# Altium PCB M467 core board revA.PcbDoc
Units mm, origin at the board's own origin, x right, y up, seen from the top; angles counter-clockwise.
Board outline 29.95 x 52.05 mm, 2 copper layers (Top Layer, Bottom Layer), stack 0.98 mm thick; 44 components, 41 nets, 229 pads, 86 vias.
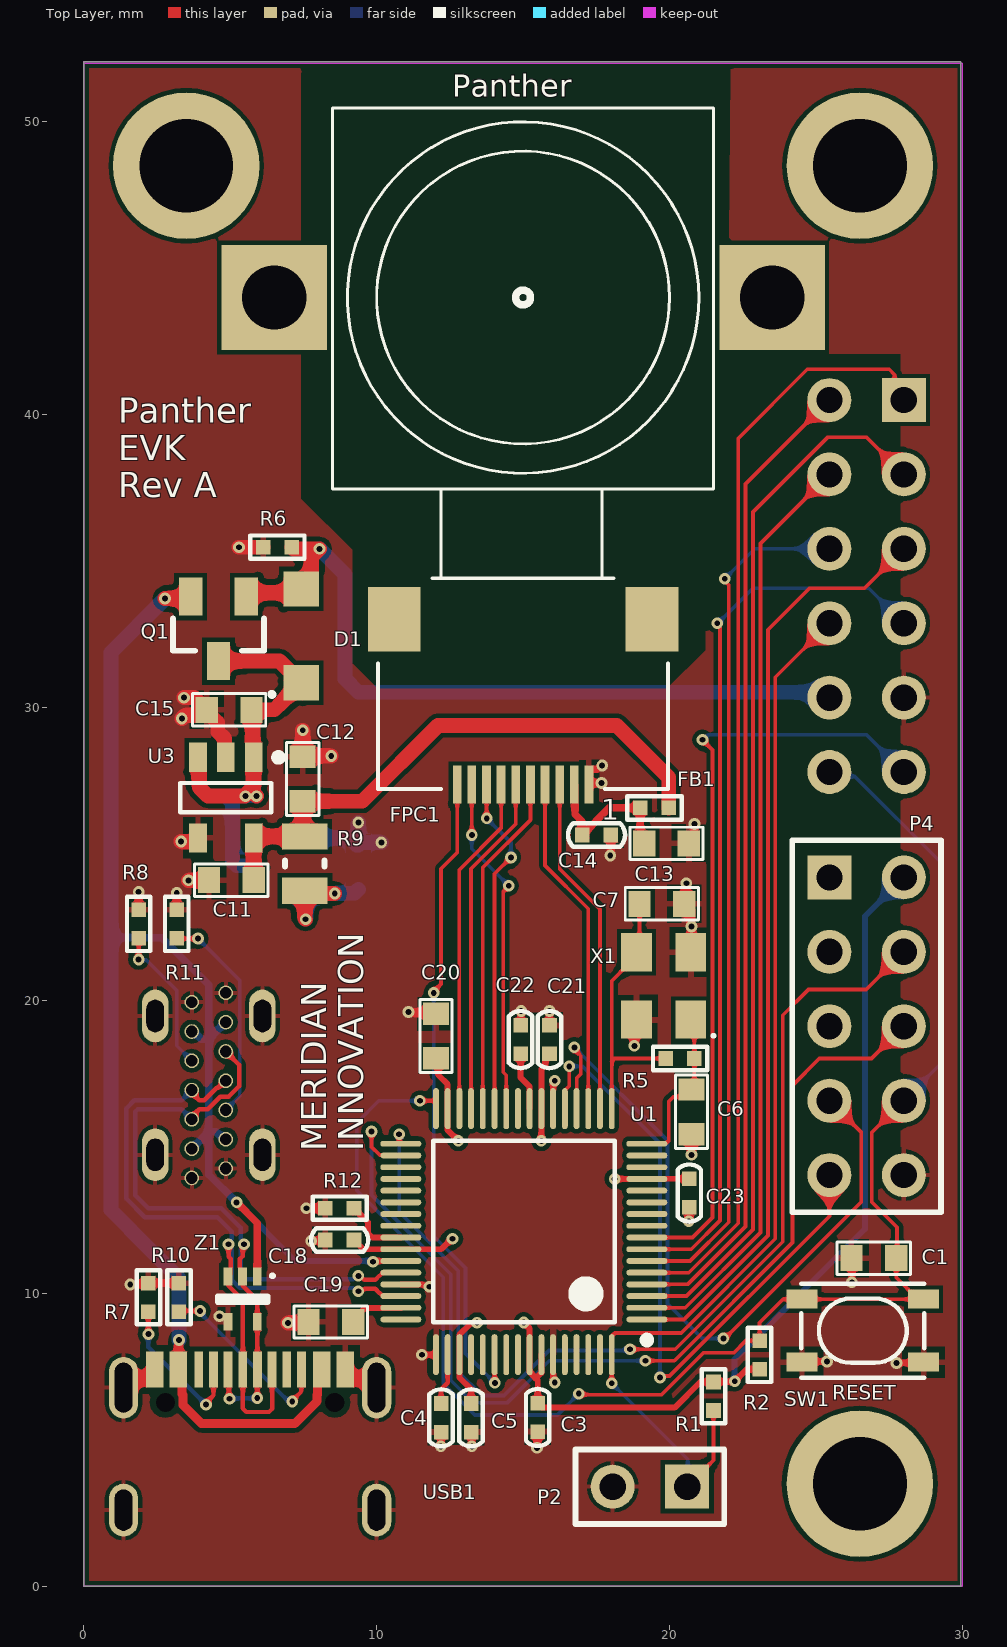
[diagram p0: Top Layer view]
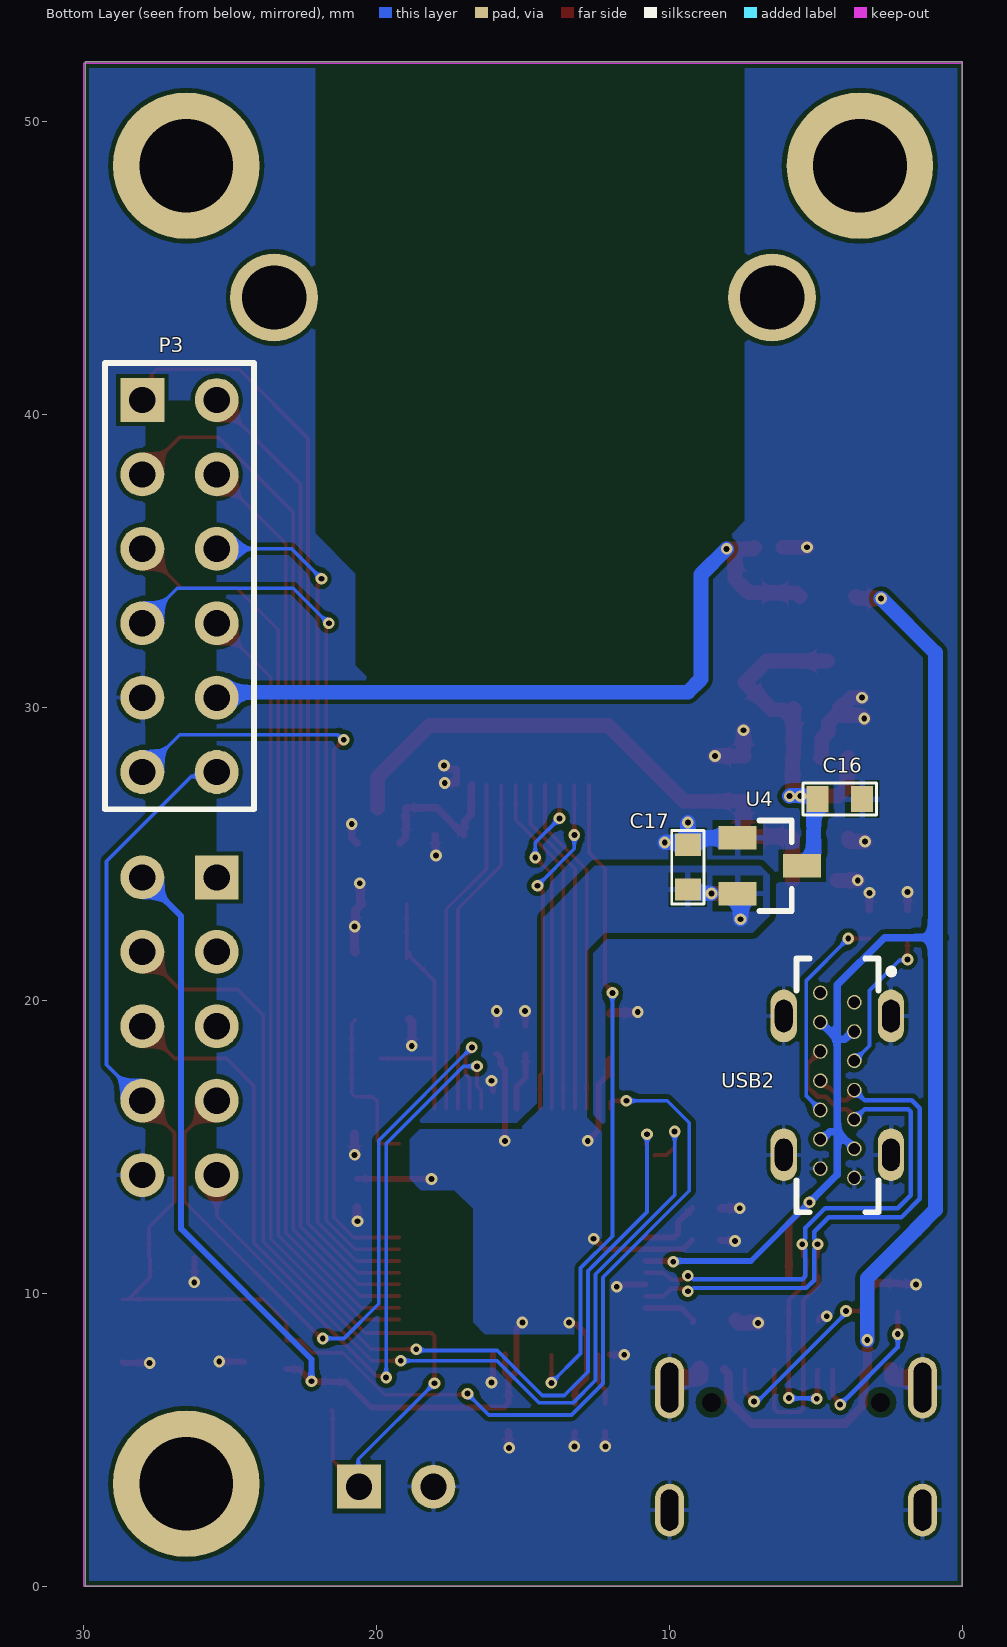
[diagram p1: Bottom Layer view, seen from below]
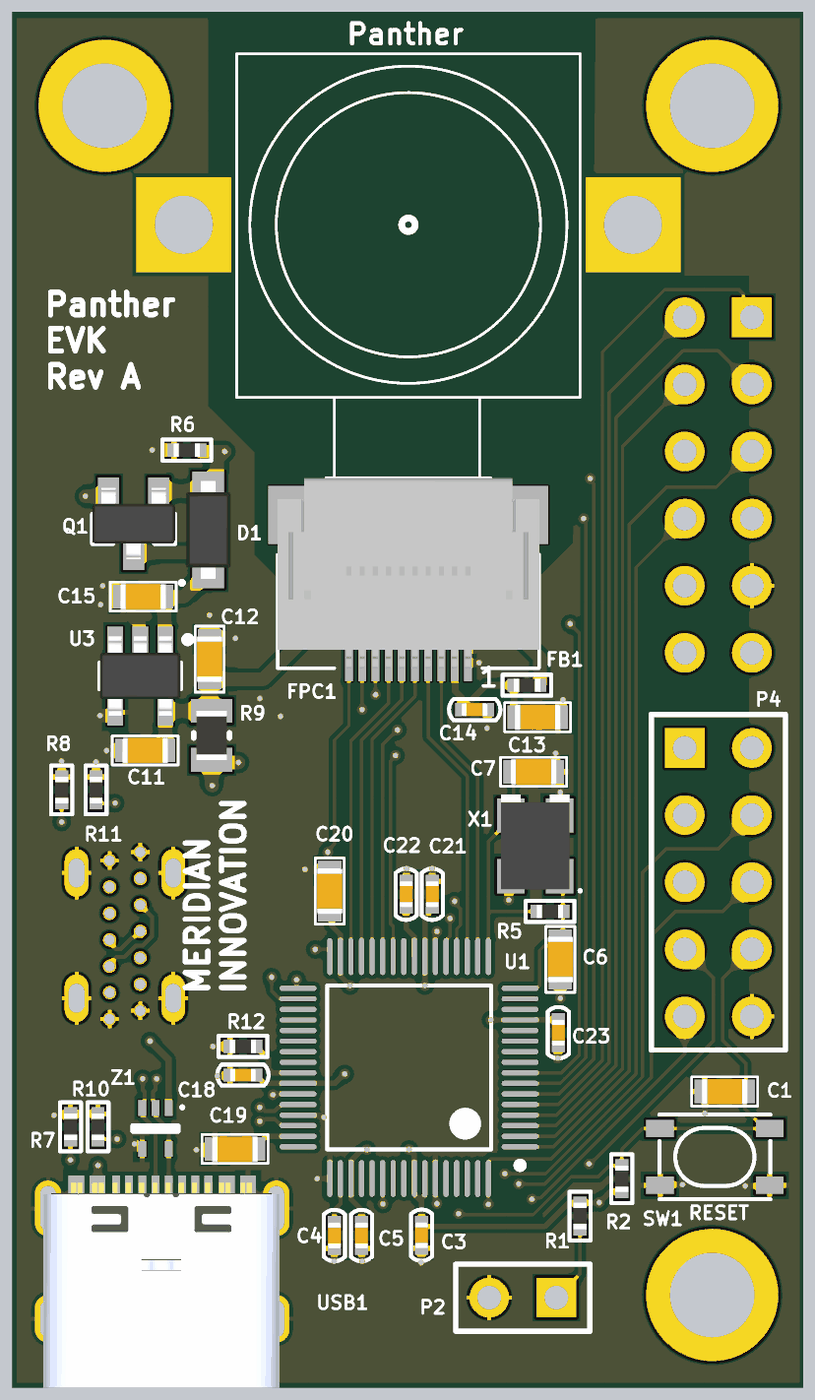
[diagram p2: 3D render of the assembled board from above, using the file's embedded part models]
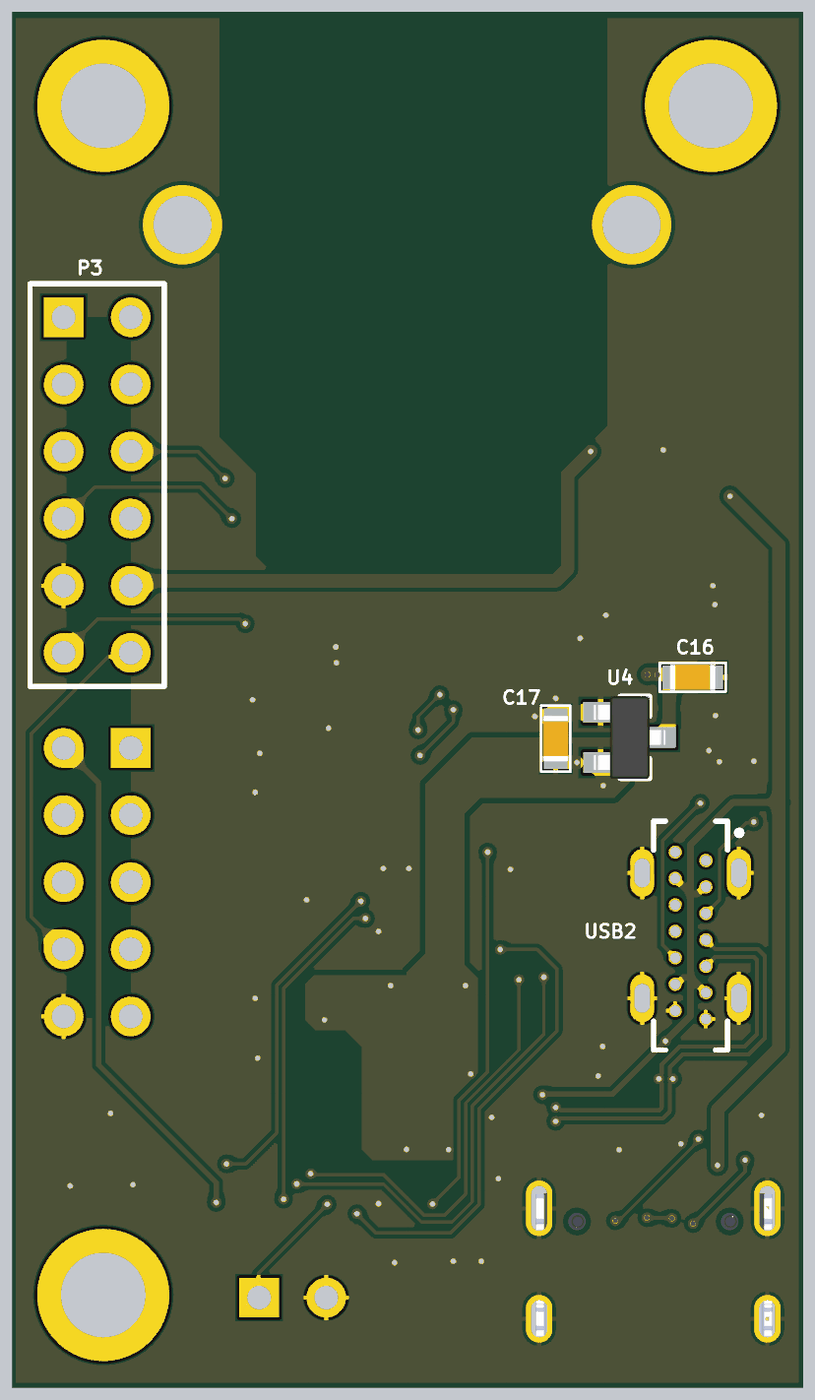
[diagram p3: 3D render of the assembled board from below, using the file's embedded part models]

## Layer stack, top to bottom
Top Solder: solder mask 0.0102, Solder Resist, Dk 3.5
Top Layer: signal copper 0.0356
Dielectric 1: dielectric 0.909, FR-4, Dk 4.8
Bottom Layer: signal copper 0.0356
Bottom Solder: solder mask 0.0102, Solder Resist, Dk 3.5

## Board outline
0,0 29.95,0 29.95,52.05 0,52.05

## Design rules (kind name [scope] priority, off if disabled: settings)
Clearance [All] p1: gap=0.152 ignorepadtopadclearanceinfootprint=FALSE except(0: Arc-Text Track-Text SMDPad-Text THPad-Text Via-Text Fill-Text Poly-Text Region-Text Text-Text Text-Hole; 0.127: Arc-Arc Arc-Track Arc-SMDPad Arc-THPad Arc-Via Arc-Hole Track-Track Track-SMDPad Track-THPad Track-Via Track-Hole SMDPad-SMDPad SMDPad-THPad SMDPad-Via SMDPad-Hole THPad-THPad THPad-Via THPad-Hole Via-Via Via-Hole; 0.2: Fill-Fill Fill-Poly Fill-Region Fill-Hole Poly-Poly Poly-Region Poly-Hole Region-Region Region-Hole)
DiffPairsRouting [All] p1: maxlimit=0.152 minlimit=0.152 mostfreqgap=0.152 toplayer_minwidth=0.152 toplayer_maxwidth=0.152 toplayer_prefwidth=0.152 bottomlayer_minwidth=0.152 bottomlayer_maxwidth=0.152 bottomlayer_prefwidth=0.152 maxuncoupledlength=12.7
HoleSize [All] p1: absolutevalues=TRUE maxlimit=4 minlimit=0.025 maxpercent=80.000 minpercent=20.000
MinimumSolderMaskSliver [All] p1: minsoldermaskwidth=0.051
PolygonConnect [All] p1: thpad.connectstyle=Relief thpad.reliefconductorwidth=0.152 thpad.reliefentries=4 thpad.polygonreliefangle="90 Angle" thpad.airgapwidth=0.127 smdpad.connectstyle=Relief smdpad.reliefconductorwidth=0.2 smdpad.reliefentries=4 smdpad.polygonreliefangle="90 Angle" smdpad.airgapwidth=0.2 via.connectstyle=Direct via.reliefconductorwidth=0.254 via.reliefentries=4 via.polygonreliefangle="90 Angle" via.airgapwidth=0.254
RoutingVias [All] p1: holewidth=0.2 width=0.4 viastyle="Through Hole" minholewidth=0.2 minwidth=0.4 maxholewidth=0.711 maxwidth=1.27
SilkToSilkClearance [All] p1: silktosilkclearance=0
SilkToSolderMaskClearance [All] p1: minsilkscreentomaskgap=0.1 clearancetoexposedcopper=TRUE
SolderMaskExpansion TentedVia [IsVia] p1: expansion=0.102 istentingtop=FALSE
SolderMaskExpansion [All] p2: expansion=0.102 istentingtop=FALSE
Width [All] p1: maxlimit=5 minlimit=0.1 preferedwidth=0.1 minimp=50.000000 maximp=50.000000 favimp=50.000000
25 further rules are at their usual default settings.

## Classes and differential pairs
component class "M467 core board revA": C1 C3 C4 C5 C6 C7 C11 C12 C13 C14 C15 C16 C17 C18 C19 C21 C22 C23 D1 FB1 FPC1 P2 P3 P4 Q1 R1 R5 R6 R7 R8 R9 R10 R11 R12 U1 U3 U4 USB1 USB2 X1 Z1
differential pair USBD: +USBD_P -USBD_N

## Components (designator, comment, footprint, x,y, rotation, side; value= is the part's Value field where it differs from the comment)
C1 "10μF" XCAM-C0603 26.975,11.2 r180 top
C3 "0.1uF" XCAM-C0402 15.5,5.763 r270 top
C4 "2.2uF" XCAM-C0402 12.2,5.75 r90 top
C5 "0.1uF" XCAM-C0402 13.225,5.75 r90 top
C6 "18pF" XCAM-C0603 20.75,16.198 r270 top
C7 "18pF" XCAM-C0603 19.738,23.3 r0 top
C11 "2.2μF" XCAM-C0603 5.038,24.105 r0 top
C12 "1uF" XCAM-C0603 7.475,27.562 r90 top
C13 "10μF" XCAM-C0603 19.894,25.364 r0 top
C14 "0.1uF" XCAM-C0402 17.509,25.65 r0 top
C15 "2.2μF" XCAM-C0603 4.963,29.925 r0 top
C16 "DNP" XCAM-C0603 4.188,26.875 r0 bottom
C17 "DNP" XCAM-C0603 9.375,24.55 r270 bottom
C18 "0.1uF" XCAM-C0402 8.738,11.821 r180 top
C19 "1uF" XCAM-C0603 8.435,9.025 r0 top
C20 "1uF" XCAM-C0603 12.025,18.784 r90 top
C21 "0.1uF" XCAM-C0402 15.9,18.665 r90 top
C22 "2.2uF" XCAM-C0402 14.915,18.665 r90 top
C23 "0.1uF" XCAM-C0402 20.675,13.425 r270 top
D1 "MBR0530" SOD123 7.425,32.45 r90 top
FB1 "BLM15HD182SN1" XCAM-R0402 19.487,26.575 r180 top
FPC1 "FH28K-10S-0.5SH" FH28K-10S-0.5SH-WITH-PANTHER 15,44 r180 top locked
P2 "MODE" HDR1X2 20.6,3.4 r180 top
P3 "EVK Header" HDR2X6 28,40.5 r270 bottom locked
P4 "Reserved Header" HDR2X5 25.46,24.2 r270 top locked
Q1 "AO3401A" SOT23 4.6,32.689 r270 top
R1 "10kR" XCAM-R0402 21.5,6.488 r90 top
R2 "10kR" XCAM-R0402 23.075,7.9 r270 top
R5 "1MR" XCAM-R0402 20.36,18.018 r0 top
R6 "100kR" XCAM-R0402 6.612,35.475 r0 top
R7 "5.1kR" XCAM-R0402 2.207,9.864 r90 top
R8 "5.1kR" XCAM-R0402 1.875,22.612 r90 top
R9 "0R" R0805 7.55,24.675 r90 top
R10 "5.1kR" XCAM-R0402 3.25,9.864 r90 top
R11 "5.1kR" XCAM-R0402 3.175,22.612 r90 top
R12 "200R" XCAM-R0402 8.738,12.907 r180 top
SW1 "SKRPABE010" "SKRP Series" 26.6,8.725 r0 top
U1 "M467SJHAN" TSQFP40P900X900X160-64N 15.025,12.107 r180 top locked
U3 "LP5907MFX-3.3/NOPB" "LP5907 SOT-23" 4.85,26.925 r270 top
U4 "DNP" SOT23 6.575,24.6 r180 bottom
USB1 "TYPE-C-GT-USB-7010ASV" GT-USB-7010ASV 10,2.6 r0 top locked
USB2 "DNP" 918-468K2029E50001 4.27,17.1 r270 bottom locked
X1 "CX3225CA12000P0HSTC1" CX3225CA 19.801,20.496 r90 top
Z1 "LC0542T5" SOT553-TI 5.425,9.8 r270 top

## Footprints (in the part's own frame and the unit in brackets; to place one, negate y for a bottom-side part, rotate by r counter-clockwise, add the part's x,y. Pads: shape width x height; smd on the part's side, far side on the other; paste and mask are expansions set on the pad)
918-468K2029E50001 [mm]
  round 0.5 hole 0.4: A1(-2.84,0.58) A4(-1.84,0.58) A5(-0.84,0.58) A6(0.16,0.58) A7(1.16,0.58) A9(2.16,0.58) A12(3.16,0.58) B1(2.84,-0.58) B4(1.84,-0.58) B5(0.84,-0.58) B6(-0.16,-0.58) B7(-1.16,-0.58) B9(-2.16,-0.58) B12(-3.16,-0.58)
  oval 1.8x0.9 hole 0.6 slot 1.1 at 0 deg: S1(-2.37,1.83) S2(2.37,1.83) S3(-2.37,-1.83) S4(2.37,-1.83)
  silkscreen extent -4.33,-1.4 4.33,1.94
CX3225CA [mm] "Kyocera Surface Mount 3225 Crystal"
  rect 1.3x1.05 smd: 1(-1.15,-0.925) 2(1.15,-0.925) 3(1.15,0.925) 4(-1.15,0.925)
  silkscreen extent -1.75,-1.75 -1.65,-1.65, body extent -1.65,-1.3 1.95,1.3, height 0.9
FH28K-10S-0.5SH-WITH-PANTHER [mm]
  rect 0.3x1.3 smd paste+0 mask+0.051: 1(-2.25,16.632) 2(-1.75,16.632) 3(-1.25,16.632) 4(-0.75,16.632) 5(-0.25,16.632) 6(0.25,16.632) 7(0.75,16.632) 8(1.25,16.632) 9(1.75,16.632) 10(2.25,16.632)
  rect 1.8x2.2 smd paste+0 mask+0.051: ""(-4.4,10.982) ""(4.4,10.982)
  silkscreen extent -6.5,-6.47 6.5,16.78, body extent -4.95,9.58 4.95,16.78, height 2.57
GT-USB-7010ASV [mm]
  rect 0.6x1.24 smd mask+0: A1(-7.57,4.8) A4(-6.77,4.8) A9(-1.87,4.8) A12(-1.07,4.8)
  rect 0.3x1.24 smd mask+0: A5(-5.57,4.8) A6(-4.57,4.8) A7(-4.07,4.8) A8(-3.07,4.8) B5(-2.57,4.8) B6(-3.57,4.8) B7(-5.07,4.8) B8(-6.07,4.8)
  oval 1x1.8 hole 0.6 slot 1.4 at 90 deg mask+0: E(-8.64,0) E(0,0)
  oval 1x2.1 hole 0.6 slot 1.7 at 90 deg mask+0: E(-8.64,4.18) E(0,4.18)
  round 0 hole 0.65 unplated mask+0: ""(-7.21,3.68) ""(-1.43,3.68)
  body extent -8.82,-2.6 0.12,5.15, height 3.26
HDR1X2 [mm] "Connector; Header; 2 Position"
  rect 1.5x1.5 hole 0.9: 1(0,0)
  round 1.5 hole 0.9: 2(2.54,0)
  silkscreen extent -1.27,-1.27 3.81,1.27
HDR2X5 [mm] "Connector; Header; 5x2 Position"
  rect 1.5x1.5 hole 0.9: 1(0,0)
  round 1.5 hole 0.9: 2(0,2.54) 3(2.54,0) 4(2.54,2.54) 5(5.08,0) 6(5.08,2.54) 7(7.62,0) 8(7.62,2.54) 9(10.16,0) 10(10.16,2.54)
  silkscreen extent -1.27,-1.27 11.43,3.81
HDR2X6 [mm] "Connector; Header; 6x2 Position"
  rect 1.5x1.5 hole 0.9: 1(0,0)
  round 1.5 hole 0.9: 2(0,2.54) 3(2.54,0) 4(2.54,2.54) 5(5.08,0) 6(5.08,2.54) 7(7.62,0) 8(7.62,2.54) 9(10.16,0) 10(10.16,2.54) 11(12.7,0) 12(12.7,2.54)
  silkscreen extent -1.27,-1.27 13.97,3.81
"LP5907 SOT-23" [mm] "SOT23, 5-Leads, Body 2.90x2.80mm, Pitch 0.95mm, IPC Medium Density"
  rect 1x0.6 smd mask+0.07: 1(-1.375,0.95) 2(-1.375,0) 3(-1.375,-0.95) 4(1.375,-0.95) 5(1.375,0.95)
  silkscreen extent -1.5,-1.55 0.5,1.93, body extent -1.5,-1.53 1.5,1.53, height 1.45
R0805 [mm] "Chip Resistor, 2-Leads, 0805"
  rect 0.9x1.55 smd: 1(-0.925,0) 2(0.925,0)
  silkscreen extent -0.1,-0.67 0.1,0.67, body extent -0.92,-0.57 0.92,0.57, height 0.6
"SKRP Series" [mm] "ALPS SMD 4-pin Tactile Switch"
  rect 1.05x0.65 smd: 1(-2.075,1.075) 2(2.075,1.075) 3(-2.075,-1.075) 4(2.075,-1.075)
  silkscreen extent -2.1,-1.6 2.1,1.6
SOD123 [mm] "SOD123, 2-Lead"
  rect 1.2x1.2 smd: 1(-1.6,0) 2(1.6,0)
  silkscreen extent -2.05,0.95 -1.95,1.05, body extent -1.85,-0.85 1.85,0.85, height 1.45
SOT23 [mm] "General Footprint for SOT23"
  rect 1.3x0.8 smd: 1(-1.1,-0.95) 2(-1.1,0.95) 3(1.1,0)
  silkscreen extent -0.35,-1.55 0.75,1.55, body extent -1.35,-1.57 1.35,1.57, height 1.3
SOT553-TI [mm] "SOT553, 5-Leads, Body 1.60x1.60mm, Pitch 0.50mm, IPC Medium Density"
  rect 0.6x0.3 smd mask+0.05: 1(-0.775,0.5) 2(-0.775,0) 3(-0.775,-0.5) 4(0.775,-0.5) 5(0.775,0.5)
  silkscreen extent -0.82,-0.85 0.1,1.03, body extent -0.65,-0.85 0.65,0.85, height 0.6
TSQFP40P900X900X160-64N [mm] "TSQFP, 64-Leads, Body 7.00x7.00mm, Pitch 0.40mm, IPC Medium Density"
  oval 1.4x0.2 smd mask+0.02: 1(-4.2,3) 2(-4.2,2.6) 3(-4.2,2.2) 4(-4.2,1.8) 5(-4.2,1.4) 6(-4.2,1) 7(-4.2,0.6) 8(-4.2,0.2) 9(-4.2,-0.2) 10(-4.2,-0.6) 11(-4.2,-1) 12(-4.2,-1.4) 13(-4.2,-1.8) 14(-4.2,-2.2) 15(-4.2,-2.6) 16(-4.2,-3) 33(4.2,-3) 34(4.2,-2.6) 35(4.2,-2.2) 36(4.2,-1.8) 37(4.2,-1.4) 38(4.2,-1) 39(4.2,-0.6) 40(4.2,-0.2) 41(4.2,0.2) 42(4.2,0.6) 43(4.2,1) 44(4.2,1.4) 45(4.2,1.8) 46(4.2,2.2) 47(4.2,2.6) 48(4.2,3)
  oval 0.2x1.4 smd mask+0.02: 17(-3,-4.2) 18(-2.6,-4.2) 19(-2.2,-4.2) 20(-1.8,-4.2) 21(-1.4,-4.2) 22(-1,-4.2) 23(-0.6,-4.2) 24(-0.2,-4.2) 25(0.2,-4.2) 26(0.6,-4.2) 27(1,-4.2) 28(1.4,-4.2) 29(1.8,-4.2) 30(2.2,-4.2) 31(2.6,-4.2) 32(3,-4.2) 49(3,4.2) 50(2.6,4.2) 51(2.2,4.2) 52(1.8,4.2) 53(1.4,4.2) 54(1,4.2) 55(0.6,4.2) 56(0.2,4.2) 57(-0.2,4.2) 58(-0.6,4.2) 59(-1,4.2) 60(-1.4,4.2) 61(-1.8,4.2) 62(-2.2,4.2) 63(-2.6,4.2) 64(-3,4.2)
  silkscreen extent -4.33,-3.1 3.1,3.82, body extent -3.5,-3.5 3.5,3.5, height 1.6
XCAM-C0402 [mm] "Chip Capacitor, 2-Leads, Body 1.00x0.50mm, as in XCAM"
  rect 0.5x0.5 smd mask+0.07: 1(-0.487,0) 2(0.487,0)
  silkscreen extent -0.97,-0.4 0.97,0.4, body extent -0.5,-0.25 0.5,0.25, height 0.35
XCAM-C0603 [mil] "Chip Capacitor, 2-Leads, Body 1.60x0.81mm, as found XCAM"
  rect 30x35 smd: 1(-30,0) 2(30,0)
  silkscreen extent -49,-22 49,22, body extent -34,-19 34,19, height 36
XCAM-R0402 [mm] "Chip Resistor, 2-Leads, Body 1.00x0.50mm, as in XCAM"
  rect 0.5x0.5 smd: 1(-0.487,0) 2(0.487,0)
  silkscreen extent -0.92,-0.4 0.92,0.4, body extent -0.5,-0.25 0.5,0.25, height 0.35

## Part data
C1 C12 C13 C19 C20: library part "Capacitor SMD", "Capacitor SMD", Dielectric=X5R, Package (Imperial)=0603, Tolerance=20%, Voltage Rating=6.3V
C3 C4 C5 C14 C18 C21 C22 C23: library part "Capacitor SMD", "Capacitor SMD", Dielectric=X5R, Package (Imperial)=0402, Tolerance=10%, Voltage Rating=6.3V
C6 C7: library part "Capacitor SMD", "Capacitor SMD", Dielectric=C0G, Package (Imperial)=0603, Tolerance=1%, Voltage Rating=50V
C11 C15: library part "Capacitor SMD", "Capacitor SMD", Dielectric=X5R, Manufacturer=TBD, Tolerance=20%, Voltage Rating=10V
C16 C17: library part "Capacitor SMD", "Capacitor SMD", Dielectric=X5R, Manufacturer=TBD, Tolerance=20%, Voltage Rating=6.3V
D1: "Surface Mount Schottky Power Rectifier"
FB1: library part "Inductor SMD", "Inductor SMD", Manufacturer=TBD
FPC1: "Hirose 0.5 mm Pitch, FPC Receptacle, 10P", Manufacturer #=FH26-15S-0.3SHW(60)
P2: library part "Header 2", "Header, 2-Pin"
P3: library part "Header 6X2", "Header, 6-Pin, Dual row"
P4: library part "Header 5X2", "Header, 5-Pin, Dual row"
Q1: "30V 4.0A P-Channel MOSFET"
R1 R2 R5 R6 R7 R8 R10 R11: library part "Resistor SMD", "Resistor SMD", Manufacturer=TBD, Tolerance=5%
R9: library part "Resistor SMD", "Resistor SMD", Manufacturer=TBD
R12: library part "Resistor SMD", "Resistor SMD", Manufacturer=TBD, Tolerance=1%
SW1: library part TACT-SW-4P, "4-pin Tactile Switch"
U1: "Nuvoton M467SJHAN"
U3: library part LP5907MFX-X.X/NOPB, "LP5907 250-mA, Ultra-Low-Noise LDO, SOT23-5 Package"
U4: library part XC6206, "Torex Positive Voltage LDO"
USB1: "5A 1 Surface Mount 16 Female -45℃~+85℃ Type-C SMD USB Connectors ROHS"
USB2: library part "USB Type-C Receptacle Straight 1", "Jing Extension of the Electronic Co. 918-468K2029E50001"
X1: library part XTAL-4P, "Passive 4-pin Oscillator"
Z1: library part TPD2E001DRLR, "Leiditech TVS Diode"

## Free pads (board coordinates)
  round 5 hole 3.2 paste-2.5: ""(3.5,48.5) ""(26.5,3.5) ""(26.5,48.5)
  round 3 hole 2.2 unplated paste-3.5 mask+0: ""(6.5,44) ""(23.5,44)
  rect 3.6x3.6 smd paste-3.6 mask+0: ""(6.5,44) ""(23.5,44)

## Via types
v1: diameter 0.4, hole 0.2, Top Layer to Bottom Layer, tented both sides, 86 vias

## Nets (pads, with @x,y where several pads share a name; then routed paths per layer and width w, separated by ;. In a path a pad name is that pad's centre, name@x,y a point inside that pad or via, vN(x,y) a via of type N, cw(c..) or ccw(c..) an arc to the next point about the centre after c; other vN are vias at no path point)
3V3_MI48: C3.1 C5.2 C17.2 C18.1 C20.1 C21.1 C23.1 P4.2 R1.2 R2.2 R9.1 U1.13 U1.23 U1.31 U1.42 U1.51 U1.57 U1.58 U4.1 | length 51
  Top Layer w0.203: C18.1 9.539,11.507 U1.42 12.204,11.507 12.562,11.865 v1(12.59,11.865) ; C20.1 12.104,17.943 12.104,17.455 12.425,17.134 U1.31 12.427,16.305 12.427,15.571 v1(12.79,15.207) ; C5.2 13.225,6.724 12.827,7.123 12.827,7.905 U1.51 12.825,8.582 13.206,8.962 13.39,8.962 v1(13.427,9) ; v1(15.025,9.007) 15.025,8.997 15.225,8.797 15.225,7.31 15.5,7.035 C3.1 15.648,6.102 15.766,6.102 15.767,6.1 20.175,6.1 21.05,6.975 R1.2 21.513,6.988 22.213,6.988 22.637,7.412 R2.2 ; 15.5,7.165 15.623,7.288 15.623,7.905 U1.58 ; v1(15.623,15.207) U1.23 ; U1.23 15.625,17.653 15.763,17.79 15.763,18.04 C21.1 ; v1(18.125,13.907) U1.13 19.822,13.907 19.827,13.912 C23.1
  Top Layer w0.508: v1(7.575,22.775) 7.55,22.8 R9.1 7.65,23.65 v1(8.57,23.65)
  Bottom Layer w0.203: v1(22.225,7) 22.225,7.75 26.675,12.2 26.675,22.875 P4.2
  Bottom Layer w0.508: v1(7.575,22.775) 7.575,23.55 U4.1 ; v1(8.57,23.65) 8.581,23.661 9.248,23.661 C17.2
5V: C15.2 C16.2 D1.1 Q1.3 U3.1 U3.3 U4.3 | length 15
  Top Layer w0.508: U3.3 3.946,28.254 3.946,27.273 4.244,26.975 v1@5.502,26.975 ; Q1.3 6.686,31.589 D1.1 6.5,29.925 6.112,29.925 C15.2@5.919,29.731 ; v1@5.502,27 5.689,27.186 v1(5.9,26.975) ; C15.2@5.763,29.963 C15.2 5.763,29.887 5.763,28.337 U3.1 v1@5.8,27.075
  Bottom Layer w0.508: U4.3 5.225,24.6 5.079,24.746 5.079,25.762 5.077,25.764 5.077,26.748 C16.2 5.05,26.975 v1(5.525,26.975) ; v1@5.525,27 5.875,27 v1(5.9,26.975)
5V_SPI_HEADER: D1.2 P3.10 Q1.2 R6.2 | length 26.2
  Top Layer w0.508: Q1.2 5.68,33.92 7.295,33.92 D1.2 7.771,34.396 7.771,35.141 v1(8.05,35.42) 7.155,35.42 R6.2
  Bottom Layer w0.508: v1(8.05,35.42) 8.925,34.545 8.925,30.975 9.375,30.525 25.275,30.525 P3.10
+3V3: C11.2 C12.1 FB1.1 R9.2 U3.5 | length 19.8
  Top Layer w0.508: C11.2 U3.5 5.8,25.554 5.846,25.6 R9.2 7.475,25.675 C12.1 9.506,26.8 12.096,29.39 18.199,29.39 19.975,27.614 FB1.1
ADDR: P3.11 U1.8 | length 26.5
  Top Layer w0.127: U1.8 20.781,11.907 21.465,12.592 21.465,28.553 21.124,28.895 v1(21.124,28.9)
  Bottom Layer w0.127: v1(21.124,28.9) 21.159,28.9 21.334,29.075 26.725,29.075 P3.11
DATA_AV: FPC1.3 U1.18 | length 11.6
  Top Layer w0.127: FPC1.3 16.25,24.487 17.625,23.112 U1.18
DATA_READY: P3.5 U1.1 | length 31.8
  Top Layer w0.127: U1.1 20.495,9.107 23.359,11.971 23.359,32.656 24.778,34.075 26.655,34.075 P3.5
DBG_UART0_RXD: P4.9 U1.21 | length 23.2
  Top Layer w0.127: U1.21 16.425,16.927 16.575,17.077 v1(16.575,17.75) ; v1(19.675,7.125) 19.727,7.177 20.002,7.177 25.46,12.635 P4.9
  Bottom Layer w0.127: v1(16.575,17.75) 17.041,17.75 19.675,15.116 v1(19.675,7.125)
DBG_UART0_TXD: P4.7 U1.20 | length 25.3
  Top Layer w0.127: v1(16.75,18.4) 16.75,18.326 16.966,18.111 16.966,17.489 16.829,17.353 16.829,16.311 U1.20 ; v1(21.839,8.461) 21.886,8.461 26.55,13.125 26.55,15.49 25.65,16.39 P4.7@25.65,16.675
  Bottom Layer w0.127: v1(16.75,18.4) 19.929,15.221 19.929,9.646 21.114,8.461 v1(21.839,8.461)
GND: C1.2 C3.2 C4.1 C5.1 C6.2 C7.2 C11.1 C12.2 C13.2 C14.2 C15.1 C16.1 C17.1 C18.2 C19.1 C20.2 C21.2 C22.2 C23.2 FPC1.1 P2.2 P3.9 P4.10 R6.1 R7.2 R8.2 R10.2 R11.2 R12.2 SW1.3 SW1.4 U1.22 U1.45 U1.49 U1.59 U3.2 U3.4 U4.2 USB1.A1 USB1.A12 USB1.E USB2.A1 USB2.A12 USB2.B1 USB2.B12 USB2.S1 USB2.S2 USB2.S3 USB2.S4 X1.2 X1.4 Z1.4 | length 36.6
  Top Layer w0.152: v1(4.634,9.219) 4.851,9.219 4.925,9.145 Z1.4
  Top Layer w0.203: U1.45 10.827,10.305 11.564,10.305 11.607,10.263 11.762,10.263 v1(11.8,10.225) ; v1(11.545,7.902) 12.023,7.902 12.025,7.904 U1.49 ; v1(12.191,4.776) 12.2,4.785 C4.1 ; C5.1 13.237,5.25 13.237,4.789 v1(13.25,4.776) ; C22.2 14.915,19.165 14.924,19.174 14.924,19.63 v1(14.934,19.639) ; C21.2 v1(15.9,19.639) ; U1.59 16.027,7.905 16.027,7.064 16.08,7.01 v1(16.08,6.957) ; U1.22@16.027,16.905 16.027,17.15 16.08,17.204 v1(16.08,17.257) ; SW1.3 24.55,7.675 v1(25.375,7.675) ; C1.2 26.225,11.188 v1(26.225,10.375) ; v1(27.75,7.625) 28.65,7.625 SW1.4
  Top Layer w0.254: v1(1.587,10.3) 1.607,10.32 2.176,10.32 R7.2 R10.2 ; R8.2 v1(1.875,23.7) ; R11.2 v1(3.175,23.675) ; USB2.S4 USB2.S4@6.1,15.005 ; v1(7.764,11.789) 7.78,11.805 8.234,11.805 C18.2 ; v1(15.475,4.725) 15.488,4.738 15.488,5.262 C3.2 ; FPC1.1@17.273,27.391 FPC1.1@17.273,27.425 ; v1(17.675,27.425) FPC1.1@17.273,27.425 ; v1(17.7,28.025) 17.66,28.025 17.526,27.891 17.273,27.891 FPC1.1@17.273,27.425 ; v1(17.975,24.95) 17.996,24.971 C14.2 ; C13.2 20.85,25.558 v1(20.85,26.025) ; P4.10 P4.10@28.149,13.891
  Top Layer w0.305: v1(7.6,12.907) R12.2 ; v1(11.084,19.605) 11.103,19.587 11.984,19.587 C20.2 ; v1(18.8,18.45) 18.8,19.269 X1.4 ; v1(20.575,24) 20.557,23.982 20.557,23.357 C7.2 20.729,23.071 20.729,22.572 20.75,22.551 v1(20.75,22.525) 20.75,21.669 X1.2 ; v1(20.656,12.462) 20.665,12.472 20.665,12.928 C23.2 ; v1(20.75,14.73) C6.2
  Top Layer w0.508: USB1.E@1.36,6.78 1.36,6.863 1.587,7.09 2.384,7.09 2.43,7.136 USB1.A1 USB1.A1@2.44,7.41 ; v1(3.325,25.425) 3.854,25.425 3.9,25.471 U3.4 ; v1(3.35,29.625) 3.46,29.734 4.074,29.734 C15.1@4.201,29.861 ; v1(3.426,30.34) 3.786,30.34 4.01,30.115 4.074,30.115 4.201,29.988 C15.1 C15.1@4.201,29.861 ; v1(3.575,24.1) 4.271,24.1 C11.1 ; U3.2 4.804,28.346 4.804,28.946 4.575,29.175 4.575,29.488 C15.1@4.201,29.861 ; v1(5.303,35.475) R6.1 ; v1(6.975,8.994) 7.642,8.994 C19.1 C19.1@7.736,9.089 ; v1(7.475,29.225) 7.475,28.374 7.45,28.349 8.449,28.349 v1(8.45,28.35) ; USB1.A12@8.976,7.446 USB1.A12 8.93,7.136 8.976,7.09 9.773,7.09 10,6.863 USB1.E@10,6.78
  Bottom Layer w0.305: v1@20.75,14.704 v1(20.75,14.73)
  Bottom Layer w0.508: U4.2 9.073,25.55 9.312,25.312 C17.1 ; v1(9.375,26.078) C17.1 ; v1(10.162,25.397) 9.46,25.397 C17.1
MODE: P2.1 P3.8 R1.1 U1.64 | length 37.8
  Top Layer w0.127: v1(18.025,6.933) U1.64 18.025,8.527 18.061,8.563 18.061,8.576 18.136,8.65 20.397,8.65 23.613,11.866 23.613,31.033 P3.8 ; P2.1@20.6,3.325 P2.1 21.5,4.3 R1.1 R1.1@21.55,6
  Bottom Layer w0.127: v1(18.025,6.933) 20.625,4.333 P2.1@20.625,3.625
NetC4_2: C4.2 U1.50 | length 1.8
  Top Layer w0.152: C4.2 12.2,6.724 12.425,6.949 U1.50
NetC19_2: C19.2 U1.47 | length 1.9
  Top Layer w0.203: C19.2 9.197,9.089 9.615,9.507 U1.47
NetC22_1: C22.1 U1.24 | length 2
  Top Layer w0.203: C22.1@14.915,18.165 14.915,17.366 15.225,17.057 U1.24
NetR7_1: R7.1 USB1.A5 | length 5.3
  Top Layer w0.152: v1(2.207,8.607) R7.1 ; v1(4.175,6.2) 4.175,6.267 4.43,6.522 USB1.A5
  Bottom Layer w0.152: v1(2.207,8.607) 2.207,8.168 v1(4.175,6.2)
NetR8_1: R8.1 USB2.A5 | length 5.1
  Top Layer w0.127: v1(1.875,21.4) R8.1
  Bottom Layer w0.127: v1(1.875,21.4) 1.902,21.373 2.147,21.373 3.175,20.345 3.175,18.455 USB2.A5
NetR10_1: R10.1 USB1.B5 | length 6.4
  Top Layer w0.127: R10.1 3.273,9.4 v1(3.975,9.4) ; v1(7.117,6.306) 7.117,6.341 7.43,6.653 USB1.B5
  Bottom Layer w0.127: v1(3.975,9.4) 3.975,9.326 6.943,6.358 7.065,6.358 v1(7.117,6.306)
NetR11_1: R11.1 USB2.B5 | length 7.4
  Top Layer w0.127: R11.1 3.187,22.113 v1(3.9,22.113)
  Top Layer w0.152: USB2.B5 USB2.B5@4.887,16.26
  Bottom Layer w0.127: v1(3.9,22.113) 5.327,20.685 5.327,16.737 USB2.B5
NetR12_1: R12.1 U1.41 | length 2.2
  Top Layer w0.203: R12.1 9.704,12.428 9.704,12.055 9.852,11.907 U1.41
nRESET: C1.1 P3.12 P4.8 R2.1 SW1.1 SW1.2 U1.32 | length 53.8
  Top Layer w0.127: v1(11.475,16.575) 11.991,16.575 12.025,16.541 U1.32 ; v1(16.9,6.575) 16.933,6.542 19.726,6.542 21.159,7.975 22.2,7.975 22.612,8.387 R2.1 23.075,9 23.875,9.8 SW1.2@28.475,9.8 ; C1.1 27.737,10.538 SW1.2@28.475,9.8 ; C1.1@27.769,11.232 27.769,12.256 26.9,13.125 26.9,15.48 P4.8 ; SW1.2 SW1.2@28.475,9.8
  Bottom Layer w0.127: v1@11.45,16.575 10.075,16.575 9.325,15.825 9.325,13.5 12.275,10.55 12.275,6.925 13.35,5.85 16.175,5.85 v1(16.9,6.575) ; P3.12 25.611,27.649 26.326,27.649 26.334,27.641 ; 26.335,27.641 29.225,24.75 29.225,17.805 P4.8
RESET_N: FPC1.9 U1.26 | length 11.7
  Top Layer w0.127: v1(13.25,25.65) FPC1.9 ; U1.26 14.425,17.445 14.319,17.551 14.319,23.708 14.51,23.898 v1(14.51,23.918)
  Bottom Layer w0.127: v1(13.25,25.65) 13.25,25.178 v1(14.51,23.918)
SCK: P3.6 U1.6 | length 29.4
  Top Layer w0.127: U1.6 20.699,11.107 22.022,12.43 22.022,34.186 21.886,34.322 v1(21.886,34.396)
  Bottom Layer w0.127: v1(21.886,34.396) 22.91,35.42 P3.6
SDA: P3.7 U1.7 | length 30.7
  Top Layer w0.127: U1.7 20.74,11.507 21.719,12.487 21.719,32.718 21.632,32.806 v1(21.632,32.88)
  Bottom Layer w0.127: v1(21.632,32.88) 21.651,32.88 22.846,34.075 26.805,34.075 P3.7
SENXOR_VDD: C13.1 C14.1 FB1.2 FPC1.2 | length 5.3
  Top Layer w0.254: FPC1.2 16.773,27.345 16.773,26.352 17,26.125 C14.1@17,25.841 ; C14.1 17.946,26.575 FB1.2 19,25.577 C13.1@19.213,25.364
SPI0_CLK: FPC1.5 U1.28 | length 11.7
  Top Layer w0.127: U1.28 13.625,24.541 15.25,26.166 FPC1.5
SPI0_CS: FPC1.8 U1.27 | length 11.6
  Top Layer w0.127: FPC1.8 13.754,27.364 13.754,26.221 v1(13.758,26.217) ; U1.27 14.025,24.324 v1(14.585,24.884)
  Bottom Layer w0.127: v1(13.758,26.217) 14.585,25.39 v1(14.585,24.884)
SPI0_MISO: FPC1.6 U1.29 | length 11.7
  Top Layer w0.127: U1.29 13.225,24.5 14.75,26.025 FPC1.6
SPI0_MOSI: FPC1.7 U1.30 | length 11.7
  Top Layer w0.127: U1.30 12.825,24.46 14.25,25.885 FPC1.7
SPI_CLK: P3.2 U1.4 | length 33.6
  Top Layer w0.127: U1.4 20.617,10.307 22.597,12.286 22.597,37.637 P3.2
SPI_MISO: P3.4 U1.2 | length 31.8
  Top Layer w0.127: U1.2 20.536,9.507 23.105,12.076 23.105,35.605 P3.4
SPI_MOSI: P3.3 U1.3 | length 35.8
  Top Layer w0.127: U1.3 20.577,9.907 22.851,12.181 22.851,36.681 25.395,39.225 26.735,39.225 P3.3
SPI_SS: P3.1 U1.5 | length 38
  Top Layer w0.127: U1.5 20.658,10.707 22.343,12.392 22.343,39.19 24.703,41.55 27.5,41.55 27.684,41.366 27.684,40.816 P3.1
SSFLASHN: FPC1.4 U1.19 | length 11.7
  Top Layer w0.127: FPC1.4 15.75,24.609 17.225,23.134 U1.19
SWCLK: P4.6 U1.34 | length 35.2
  Top Layer w0.127: v1(9.825,15.525) 9.825,15 10.104,14.721 10.504,14.721 U1.34@10.52,14.705 ; v1(19.175,7.7) 20.166,7.7 24.2,11.734 24.2,17.101 25.114,18.016 26.896,18.016 P4.6
  Bottom Layer w0.127: v1(9.825,15.525) 9.825,13.359 12.529,10.655 12.529,7.03 13.298,6.261 14.451,6.261 15.89,7.7 v1(19.175,7.7)
SWDIO: P4.4 U1.33 | length 35.7
  Top Layer w0.127: v1(10.768,15.432) 10.768,15.141 10.802,15.107 U1.33 ; v1(18.65,8.09) 20.197,8.09 23.867,11.76 23.867,19.499 24.742,20.374 26.714,20.374 P4.4
  Bottom Layer w0.127: v1(10.768,15.432) 10.768,12.775 12.783,10.76 12.783,7.326 13.594,6.515 14.346,6.515 15.881,8.05 18.61,8.05 v1(18.65,8.09)
SYSCLK: FPC1.10 U1.54 | length 22.6
  Top Layer w0.127: v1(11.95,20.26) 11.95,20.312 12.2,20.562 12.2,24.5 12.75,25.05 FPC1.10 ; U1.54 14.03,7.902 14.03,6.949 v1(14.035,6.944)
  Bottom Layer w0.127: v1(11.95,20.26) 11.95,11.953 13.037,10.866 13.037,7.942 v1(14.035,6.944)
USB_5V: Q1.1 U1.43 USB1.A4 USB1.A9 USB2.A4 USB2.A9 USB2.B4 USB2.B9 Z1.1 | length 60.7
  Top Layer w0.203: v1(9.875,11.078) 9.902,11.105 10.823,11.105 U1.43
  Top Layer w0.254: v1(5.22,13.107) 5.925,12.402 Z1.1
  Top Layer w0.305: v1@3.242,8.415 v1(3.25,8.407) 3.24,8.397 3.24,7.41 USB1.A4 3.378,7.252 3.356,7.231 3.356,6.569 3.394,6.53 3.394,6.181 4.025,5.55 7.2,5.55 7.966,6.316 7.966,6.53 7.982,6.547 7.982,7.252 USB1.A9
  Top Layer w0.508: v1(2.775,33.725) 3.586,33.725 Q1.1
  Bottom Layer w0.203: v1(5.22,13.107) 7.22,11.107 9.846,11.107 v1(9.875,11.078)
  Bottom Layer w0.254: 0.925,22.146 2.659,22.146 4.27,20.535 4.27,18.68 ; USB2.A9 4.27,15.52 ; USB2.A4 3.757,18.94 4.017,18.68 4.27,18.68 ; USB2.B4 4.783,15.26 4.523,15.52 4.27,15.52 ; USB2.B9 4.27,18.68 ; v1(5.22,13.107) 4.27,14.057 4.27,15.52 ; 4.27,15.52 4.27,18.68
  Bottom Layer w0.508: 1.593,12.168 3.25,10.511 v1(3.25,8.407) ; 1.6,12.175 0.925,12.85 0.925,22.146 0.925,31.875 v1(2.775,33.725)
USBD_N: U1.44 USB1.A7 USB1.B7 USB2.A7 USB2.B7 Z1.2 Z1.5 | length 27.5
  Top Layer w0.152: USB2.A7 3.69,16.034 3.944,16.288 4.237,16.288 4.662,16.713 4.944,16.713 5.303,17.072 5.303,17.807 USB2.B7 ; USB1.B7 4.952,7.377 4.952,6.422 v1(4.975,6.4) ; v1(5.471,11.679) 5.428,11.636 5.428,11.274 5.327,11.174 5.327,10.888 5.351,10.864 5.351,10.649 Z1.2 5.425,10.262 5.925,9.763 Z1.5 5.928,9.022 5.928,6.428 v1(5.925,6.425) ; v1(9.375,10.598) 9.442,10.598 9.581,10.459 9.949,10.459 10.099,10.61 10.115,10.61 10.212,10.707 U1.44
  Bottom Layer w0.152: USB2.A7 3.342,16.288 2.53,16.288 1.851,16.288 1.762,16.198 1.762,13.352 2.207,12.907 4.69,12.907 5.364,12.233 5.364,11.857 5.475,11.746 v1@5.475,11.679 ; v1(4.975,6.4) 4.988,6.413 5.913,6.413 v1(5.925,6.425) ; v1(5.471,11.679) 5.471,11.612 5.364,11.505 5.364,10.577 5.454,10.487 9.197,10.487 9.308,10.598 v1(9.375,10.598)
USBD_P: U1.46 USB1.A6 USB1.B6 USB2.A6 USB2.B6 Z1.3 | length 27.5
  Top Layer w0.152: USB2.A6 3.784,16.94 3.757,16.912 3.757,16.779 3.944,16.592 4.11,16.592 4.536,17.018 4.587,17.018 4.829,17.26 USB2.B6 ; v1(4.944,11.679) 4.948,11.674 4.948,11.248 5.023,11.174 5.023,10.888 4.999,10.864 4.999,10.649 Z1.3 4.925,10.275 5.43,9.77 5.43,6.07 5.55,5.95 6.325,5.95 6.43,6.055 USB1.B6 ; v1(9.375,10.071) 9.422,10.119 9.553,10.119 9.588,10.154 9.949,10.154 10.099,10.004 10.115,10.004 10.212,9.907 U1.46
  Bottom Layer w0.152: USB2.A6 3.342,16.592 2.656,16.592 1.725,16.592 1.457,16.325 1.457,13.226 2.081,12.602 4.564,12.602 5.059,12.107 5.059,11.857 4.948,11.746 v1@4.948,11.679 ; v1(4.944,11.679) 4.944,11.616 5.059,11.501 5.059,10.45 5.327,10.183 9.197,10.183 9.308,10.071 v1(9.375,10.071)
XTAL_IN: C7.1 R5.1 U1.17 X1.3 | length 9.5
  Top Layer w0.127: U1.17 18.025,17.926 ; X1.3 18.876,21.521 18.025,20.669 18.025,17.926 ; X1.3@18.976,21.421 C7.1 ; R5.1 18.118,18.018 18.025,17.926
XTAL_OUT: C6.1 R5.2 U1.16 X1.1 | length 5.7
  Top Layer w0.127: U1.16 19.845,15.107 19.881,15.143 19.901,15.143 19.975,15.218 19.975,16.55 20.138,16.713 20.729,16.713 20.848,16.832 R5.2 20.848,19.224 X1.1
pads on no net: FPC1. P4.1 P4.3 P4.5 U1.9 U1.10 U1.11 U1.12 U1.14 U1.15 U1.25 U1.35 U1.36 U1.37 U1.38 U1.39 U1.40 U1.48 U1.52 U1.53 U1.55 U1.56 U1.60 U1.61 U1.62 U1.63 USB1. USB1.A8 USB1.B8

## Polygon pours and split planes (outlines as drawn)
3V3_MI48 on Bottom Layer "NONET_L-01_P-001" (solid, pour order 26): 16.309,8.607 16.709,9.007 16.709,12.884 17.35,13.525 18.494,13.525 18.876,13.907 18.863,13.92 18.863,15.269 18.525,15.607 15.025,15.607 15.025,15.707 14.319,16.413 14.319,22.83 12.549,24.6 6.9,24.6 6.575,24.275 6.575,22.89 7.155,22.31 12.22,22.31 12.825,21.705 12.825,16.005 12.321,15.501 12.321,14.703 12.321,11.557 12.975,10.903 12.975,8.857 13.225,8.607
GND on Bottom Layer "Bottom Layer-GND" (solid, remove dead copper, pour order 30): 0,0 30,0 30,52.05 0,52.05
GND on Top Layer "Bottom Layer-GND" (solid, remove dead copper, pour order 24): 0,0 30,0 30,52.05 0,52.05

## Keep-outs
Keep-Out Layer:
  lines w0.05: 0,52 30,52 30,0 ; 0,52.05 0,0 30,0 ; 30,0 30,0 ; 30,0 30,0

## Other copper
Top Layer:
  pour cut-out: 7.413,51.668 7.413,37.137 9.163,35.387 9.163,31.518 10.038,30.643 19.913,30.643 21.23,31.959 21.267,34.533 21.928,35.079 22.088,51.793 7.538,51.793
  pour cut-out: 25.46,13.975 27.9,13.975 27.9,42.075 25.46,42.075
Bottom Layer:
  pour cut-out: 7.425,51.925 7.425,36.375 9.2,34.6 9.2,31.475 10.025,30.65 19.925,30.65 20.725,31.45 20.725,34.575 22.1,35.95 22.1,52.05 7.55,52.05
  pour cut-out: 25.46,13.975 27.9,13.975 27.9,40.5 25.46,40.5

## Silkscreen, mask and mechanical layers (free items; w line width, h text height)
Top Overlay:
  text "Panther / EVK / Rev A" at 1.175,37.175 h0.85
  text "MERIDIAN / INNOVATION" at 9.55,14.85 h0.85 r90
  text "RESET" at 25.55,6.375 h0.5
Mechanical 11:
  circle w0.025: c26.5,48.5 r2.25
